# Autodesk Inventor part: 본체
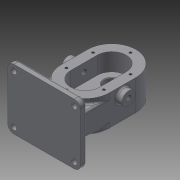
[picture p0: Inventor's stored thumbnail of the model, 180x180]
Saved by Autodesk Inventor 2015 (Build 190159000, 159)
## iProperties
Created: 2020-09
Part Number: 본체
Material: 일반
Document SubType Name: Modeling
Designer: Lineart
Density: 1 g/cm^3
Appearance: 기본값
Mass: 533.123 g
Surface Area: 786.226 cm^2
Volume: 533.123 cm^3
Author: Lineart
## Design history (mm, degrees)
sketch "스케치1"
  geometry: L1 (0, 0)-(120, 0); L2 (120, 0)-(120, -100); L3 (120, -100)-(0, -100); L4 (0, -100)-(0, 0)
  constraints: 8 end point, 2 parallel, 1 horizontal, 1 perpendicular
  dimensions: "d0" = 100 distance of L1.end L2.end; "d1" = 120 distance of L2.end L3.end
extrude "돌출1" new body sketch "스케치1" distance "d2" = 10; taper "d3" = 0 deg
fillet "모깎기1" dims "d4" = 10
fillet "모깎기2" dims "d5" = 3
hole "구멍1" diameter "d8" = 9; stored, may be unused: countersink angle "d12" = 90 deg, drill point angle "d14" = 118 deg; dims "d6" = 10, "d7" = 10, "d9" = 6, "d10" = 4, "d11" = 2, "d13" = 18.5
hole "구멍2" diameter "d17" = 9; stored, may be unused: countersink angle "d21" = 90 deg, drill point angle "d23" = 118 deg; dims "d15" = 10, "d16" = 10, "d18" = 6, "d19" = 4, "d20" = 2, "d22" = 18.5
hole "구멍3" diameter "d26" = 9; stored, may be unused: countersink angle "d30" = 90 deg, drill point angle "d32" = 118 deg; dims "d24" = 10, "d25" = 10, "d27" = 6, "d28" = 4, "d29" = 2, "d31" = 18.5
hole "구멍4" diameter "d35" = 9; stored, may be unused: countersink angle "d39" = 90 deg, drill point angle "d41" = 118 deg; dims "d33" = 10, "d34" = 10, "d36" = 6, "d37" = 4, "d38" = 2, "d40" = 18.5
node "작업 평면1"
sketch "스케치2"
  geometry: L1 (-120, 90)-(-120, 10) reference; L2 (-110, 0)-(-10, 0) reference; 2 further points
  constraints: 1 other
  dimensions: "d43" = 60 distance from line of L1 point (-60, 12); "d44" = 12 distance from line of L2 point (-60, 12)
feature "엠보싱1" sketch "스케치2" dims "d0" = 100, "d1" = 120, "d45" = 0.5, "d46" = 0
sketch "스케치3"
  geometry: L1 (100, 0)-(0, 0) reference; C1 r 19 at (50, 112); 2 further points
  constraints: 1 centre point, 1 midpoint, 1 vertical alignment
  dimensions: "d47" = 112 distance from line of L1 C1.centre; "d48" = 38 diameter of C1
extrude "돌출2" join sketch "스케치3" distance "d49" = 17; taper "d50" = 0 deg; dims "d40" = 18.5
sketch "스케치4"
  geometry: L1 (-40, 0)-(-40, -44); L2 (40, 0)-(40, -44); C1 r 19 at (0, 0) reference; A1 r 40 centre (0, 0) between (40, 0) and (-40, 0); A2 r 40 centre (0, -44) between (-40, -44) and (40, -44); 1 further point
  constraints: 4 end point, 4 point on circle, 2 centre point, 2 tangent, 2 vertical, 1 coincident, 1 vertical alignment
  dimensions: "d51" = 80 diameter of A1; "d52" = 80 diameter of A2; "d53" = 44 distance of A2.centre C1.centre
extrude "돌출3" join sketch "스케치4" distance "d54" = 53; taper "d55" = 0 deg
sketch "스케치5"
  geometry: L1 (0, 0)-(0, -44); L2 (-24, 0)-(-24, -44); L3 (24, -44)-(24, 0); A1 r 40 centre (0, 0) between (40, 0) and (-40, 0) reference; A2 r 40 centre (0, -44) between (-40, -44) and (40, -44) reference; A3 r 24 centre (0, 0) between (24, 0) and (-24, 0); A4 r 24 centre (0, -44) between (-24, -44) and (24, -44); 2 further points
  constraints: 8 end point, 4 point on circle, 4 tangent, 2 centre point, 1 midpoint, 1 parallel, 1 vertical
  dimensions: "d56" = 48 diameter of A4
extrude "돌출4" cut sketch "스케치5" distance "d57" = 29; taper "d58" = 0 deg
hole "구멍5" diameter "d61" = 25; stored, may be unused: countersink angle "d65" = 90 deg, drill point angle "d67" = 0 deg; dims "d59" = 10, "d60" = 10, "d62" = 6, "d63" = 4, "d64" = 2, "d66" = 15
hole "구멍6" diameter "d70" = 25; stored, may be unused: countersink angle "d74" = 90 deg, drill point angle "d76" = 0 deg; dims "d68" = 10, "d69" = 10, "d71" = 6, "d72" = 4, "d73" = 2, "d75" = 15
chamfer "모따기1" distance "d77" = 1; stored, may be unused: second distance "d78" = 2, angle "d79" = 45 deg
hole "구멍7" diameter "d82" = 28; stored, may be unused: countersink angle "d86" = 90 deg, drill point angle "d88" = 0 deg; dims "d80" = 10, "d81" = 10, "d83" = 6, "d84" = 4, "d85" = 2, "d87" = 7.3
chamfer "모따기2" distance "d89" = 0.7; stored, may be unused: second distance "d90" = 2, angle "d91" = 30 deg
fillet "모깎기3" dims "d92" = 0.5
hole "구멍8" diameter "d95" = 17; stored, may be unused: countersink angle "d99" = 90 deg, drill point angle "d101" = 0 deg; dims "d93" = 10, "d94" = 10, "d96" = 6, "d97" = 4, "d98" = 2, "d100" = 24.55
fillet "모깎기4" dims "d102" = 3
sketch "스케치6"
  geometry: L1 (0, 0)-(0, -44); L2 (-31, 0)-(-31, -44); L3 (31, -44)-(31, 0); A1 r 40 centre (0, 0) between (40, 0) and (-40, 0) reference; A2 r 40 centre (0, -44) between (-40, -44) and (40, -44) reference; A3 r 31 centre (0, 0) between (31, 0) and (-31, 0); A4 r 31 centre (0, -44) between (-31, -44) and (31, -44); 8 further points
  constraints: 8 end point, 7 point on circle, 4 horizontal alignment, 4 tangent, 3 point on line, 2 centre point, 1 midpoint, 1 parallel, 1 vertical
  dimensions: "d103" = 62 diameter of A4
hole "구멍9" sketch "스케치6" at (0, 31), (0, -75), (-31, 0), (-31, -44), (31, 0), (31, -44) diameter "d104" = 4.134; stored, may be unused: countersink angle "d108" = 90 deg, drill point angle "d110" = 118 deg; dims "d105" = 10, "d106" = 4, "d107" = 2, "d109" = 12
sketch "스케치7"
  geometry: L1 (50, 84)-(0, 84) reference; L2 (0, 44)-(0, 68) reference; L3 (0, 0)-(0, 44) reference; C1 r 11 at (14, 22); 2 further points
  constraints: 1 centre point, 1 midpoint
  dimensions: "d111" = 22 diameter of C1; "d112" = 22 vertical distance of C1.centre L2.start; "d129" = 14 distance from line of L3 C1.centre
extrude "돌출5" join sketch "스케치7" distance "d113" = 10; taper "d114" = 0 deg
sketch "스케치8"
  geometry: C1 r 11 at (-14, 22) reference; 1 further point
extrude "돌출6" join sketch "스케치8" distance "d115" = 10; taper "d116" = 0 deg
fillet "모깎기5" dims "d117" = 3
hole "구멍10" diameter "d120" = 8.917; stored, may be unused: countersink angle "d124" = 90 deg, drill point angle "d126" = 0 deg; dims "d121" = 113, "d122" = 4, "d123" = 2, "d125" = 113.5, "d130" = 10, "d131" = 10
sketch "스케치9"
  geometry: L1 (-100, 75)-(-20, 75); L2 (-20, 75)-(-20, 38); L3 (-20, 38)-(-100, 38); L4 (-100, 38)-(-100, 75); L5 (-10, 100)-(-110, 100) reference; L6 (-110, 0)-(-10, 0) reference; 3 further points
  constraints: 8 end point, 2 midpoint, 2 parallel, 1 horizontal, 1 perpendicular, 1 vertical alignment
  dimensions: "d132" = 25 distance between parallel lines of L5 L1; "d133" = 37 distance of L1.end L2.end; "d134" = 80 distance of L2.end L3.end
extrude "돌출7" join sketch "스케치9" stored distance "d135" = 10; taper "d136" = 0 deg
fillet "모깎기6" dims "d137" = 3
fillet "모깎기7" dims "d138" = 3
fillet "모깎기8" dims "d139" = 3
node "솔리드1"
node "투영된 루프1"
other parameters: "d42" = 37.5
